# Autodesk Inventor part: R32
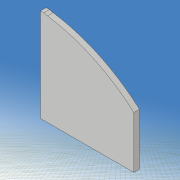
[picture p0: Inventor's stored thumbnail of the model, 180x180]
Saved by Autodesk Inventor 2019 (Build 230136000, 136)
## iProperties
Created: 2021-05
Part Number: R32
Material: 一般
Document SubType Name: Modeling
Designer: kikut
Density: 1 g/cm^3
Appearance: 既定
Mass: 0.06 g
Surface Area: 2.24 cm^2
Volume: 0.06 cm^3
Author: kikut
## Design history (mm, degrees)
sketch "スケッチ1"
  geometry: L1 (80, 60)-(-80, 60); L2 (-80, 60)-(-80, -60); L3 (-80, -60)-(80, -60); L4 (80, -60)-(80, 60); L5 (80, 60)-(-80, -60); L6 (-80, 60)-(80, -60); 1 further point
  constraints: 12 end point, 2 midpoint, 2 parallel, 1 horizontal, 1 perpendicular
  dimensions: "d0" = 160 distance of L2.end L3.end; "d1" = 120 distance of L1.end L2.end
extrude "押し出し1" new body sketch "スケッチ1" stored distance "d2" = 0.6; taper "d3" = 0 deg
sketch "スケッチ2"
  geometry: L1 (-140, 0)-(140, 0) reference; L2 (0, -54)-(20, -30); L3 (0, 54)-(20, 30); L4 (0, -3)-(6.514, -3); L5 (6.514, -3)-(16, -6); L6 (16, -6)-(24, -3); L7 (24, -3)-(33.716, -3); L8 (0, 3)-(6.514, 3); L9 (6.514, 3)-(16, 6); L10 (16, 6)-(24, 3); L11 (24, 3)-(33.716, 3); L12 (0, -98)-(0, 98) reference; L13 (-100, -70)-(100, -70); L14 (100, -70)-(100, 70); L15 (100, 70)-(-100, 70); L16 (-100, 70)-(-100, -70); L17 (-100, -70)-(100, 70); L18 (100, -70)-(-100, 70); A1 r 60 centre (54.312, 28.5) between (0, 54) and (0, 3); A2 r 60 centre (54.312, -28.5) between (0, -3) and (0, -54); A3 r 18.111 centre (18, -12) between (20, -30) and (33.716, -3); A4 r 18.111 centre (18, 12) between (33.716, 3) and (20, 30); 1 further point
  constraints: 32 end point, 8 point on circle, 8 symmetric about line, 4 centre point, 3 horizontal, 2 collinear, 2 midpoint, 2 parallel, 1 perpendicular
  dimensions: "d5" = 60 radius of A1; "d6" = 6 distance of L8.start L4.start; "d7" = 108 distance of L3.start L2.start; "d8" = 0 horizontal distance of L3.start L8.start; "d9" = 60 distance of L3.end L2.end; "d10" = 0 horizontal distance of point (0, 0) L3.start; "d11" = 20 horizontal distance of L3.start L3.end; "d12" = 24 distance of A4.centre A3.centre; "d13" = 6 distance of L11.end L7.end; "d14" = 12 distance of L9.end L5.end; "d15" = 16 distance from line of L12 L5.end; "d16" = 24 distance from line of L6.end L12; "d17" = 200 distance of L14.end L15.end; "d18" = 140 distance of L15.end L13.start; "d30" = 18 distance from line of L12 A4.centre
extrude "押し出し2" cut sketch "スケッチ2" stored distance "d19" = 10; taper "d20" = 0 deg
sketch "スケッチ3"
  geometry: L1 (49.705, -17.97)-(33.948, -15.191); L2 (33.948, -15.191)-(34.295, -13.222); L3 (34.295, -13.222)-(50.052, -16); L4 (50.052, -16)-(49.705, -17.97); L5 (49.705, -17.97)-(34.295, -13.222); L6 (33.948, -15.191)-(50.052, -16); L7 (50.052, 16)-(34.295, 13.222); L8 (34.295, 13.222)-(33.948, 15.191); L9 (33.948, 15.191)-(49.705, 17.97); L10 (49.705, 17.97)-(50.052, 16); L11 (50.052, 16)-(33.948, 15.191); L12 (34.295, 13.222)-(49.705, 17.97); L13 (-112, 0)-(112, 0) reference; L14 (0, -84)-(0, 84) reference; 3 further points
  constraints: 24 end point, 4 midpoint, 4 parallel, 2 perpendicular, 2 symmetric about line
  dimensions: "d21" = 2 distance of L3.end L1.start; "d22" = 2 distance of L9.end L7.start; "d23" = 16 distance of L8.end L9.end; "d24" = 42 distance from line of L14 point (42, 15.596); "d26" = 10 deg angle of L7 L13; "d62" = 16 distance from line of L3.end L13
extrude "押し出し3" join sketch "スケッチ3" distance "d27" = 0.6; taper "d28" = 0 deg
fillet "フィレット1" dims "d31" = 2
fillet "フィレット2" dims "d32" = 1
sketch "スケッチ6"
  geometry: L1 (-20, 60)-(80, 60); L2 (80, 60)-(80, -60); L3 (80, -60)-(-20, -60); L4 (-20, -60)-(-20, 60); L5 (-46.168, 0)-(93.832, 0) reference; L6 (0, -84)-(0, 84) reference; L7 (20, 20)-(30, 20); L8 (30, 20)-(30, 30); L9 (30, 30)-(20, 30); L10 (20, 30)-(20, 20); 1 further point
  constraints: 16 end point, 4 parallel, 2 horizontal, 2 perpendicular, 1 other
  dimensions: "d63" = 120 distance of L3.end L1.start; "d64" = 100 distance of L1.start L1.end; "d65" = 20 distance between parallel lines of L6 L4; "d66" = 10 distance of L8.end L9.end; "d73" = 10 distance of L9.end L7.start; "d74" = 20 distance between parallel lines of L7 L5; "d75" = 40 distance between parallel lines of L10 L4
extrude "押し出し4" cut sketch "スケッチ6" stored distance "d70" = 10; taper "d71" = 0 deg
node "ソリッド1"
